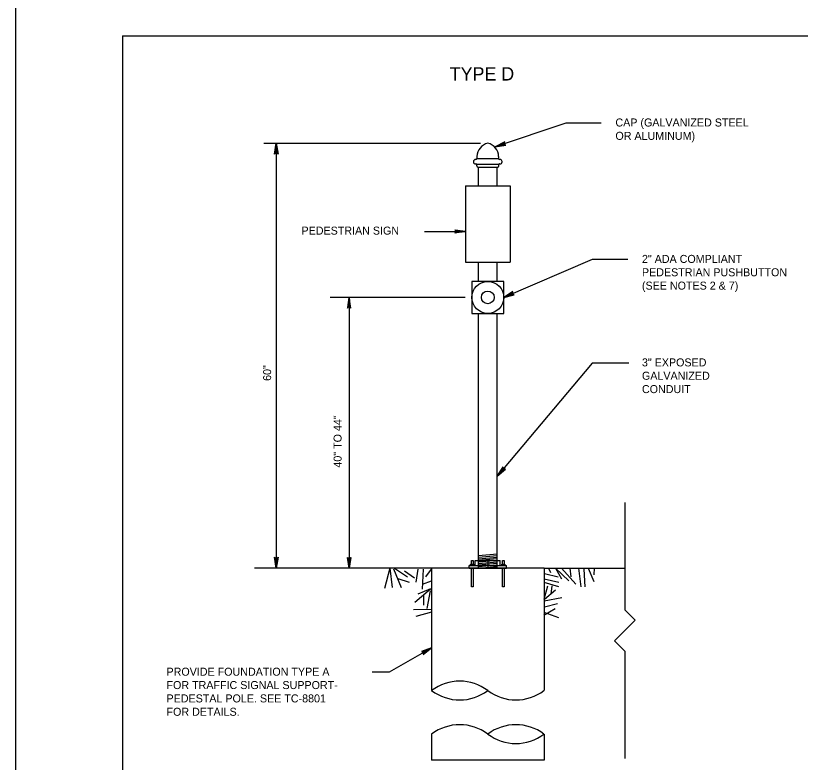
# Model space of a CAD drawing. Extents: x 36 to 940, y -1166 to 1210.
# Drawn here: x 35.9 to 329.9, y -265 to 14.7 of the extents above; entities that cross this region are included whole.
import ezdxf

# ---------------------------------------------------------------- set-up
doc = ezdxf.new("R2010")
doc.units = 0
for name, color, linetype in [('1', 7, 'Continuous'), ('2', 7, 'Continuous'), ('Default', 7, 'Continuous'), ('PLT-BNDY', 7, 'Continuous')]:
    doc.layers.add(name, color=color, linetype=linetype)

msp = doc.modelspace()

# ---------------------------------------------------------------- linework, layer by layer
at = {"layer": '1'}
for p, q in [((75.86, 7.17), (861.86, 7.17)), ((75.86, 7.17), (75.86, -556.83)), ((242.01, -25.54), (215.51, -34.47)), ((255.28, -25.54), (242.01, -25.54)), ((189.11, -66.13), (204.45, -66.13)), ((251.95, -76.64), (218.77, -90.85)), ((265.22, -76.64), (251.95, -76.64)), ((204.34, -90.85), (153.7, -90.85)), ((160.78, -90.85), (160.78, -192.24)), ((251.95, -115.43), (216.31, -157.79)), ((265.61, -115.43), (251.95, -115.43)), ((209.29, -187.54), (216.31, -186.93)), ((209.29, -188.13), (216.31, -187.52)), ((209.29, -188.72), (216.31, -188.1)), ((208.12, -191.3), (208.12, -189.43)), ((208.12, -189.43), (217.48, -189.43)), ((208.12, -191.3), (208.12, -189.43)), ((209.29, -189.3), (216.31, -188.69)), ((209.29, -189.89), (216.31, -189.28)), ((209.29, -190.48), (216.31, -189.86)), ((209.29, -191.06), (216.31, -190.45)), ((209.29, -191.65), (216.31, -191.04)), ((217.48, -191.3), (217.48, -189.43)), ((217.48, -191.3), (217.48, -189.43)), ((191.74, -192.24), (125.38, -192.24)), ((176.04, -192.24), (174.1, -199.82)), ((176.06, -192.32), (176.95, -199.48)), ((177.5, -192.5), (180.35, -199.48)), ((177.84, -192.32), (182.68, -195.53)), ((181.6, -193.21), (185.37, -195.9)), ((186.54, -192.68), (185.83, -197.5)), ((188.52, -192.68), (188.16, -200.19)), ((191.56, -192.68), (189.41, -195.53)), ((233.86, -192.24), (191.74, -192.24)), ((191.74, -192.24), (191.74, -238.1)), ((205.79, -192.24), (205.79, -191.3)), ((205.79, -191.3), (219.81, -191.3)), ((205.79, -192.24), (205.79, -191.3)), ((205.79, -192.24), (219.81, -192.24)), ((209.29, -192.24), (216.31, -191.62)), ((219.81, -192.24), (219.81, -191.3)), ((219.81, -192.24), (219.81, -191.3)), ((233.86, -192.24), (233.86, -238.1)), ((233.86, -192.24), (264.18, -192.24)), ((235.58, -192.24), (236.26, -193.92)), ((238.22, -192.31), (240.37, -196.25)), ((238.22, -192.31), (243.22, -196.96)), ((240.46, -192.24), (245.73, -198.21)), ((243.58, -192.31), (243.93, -195.52)), ((246.8, -192.31), (247.69, -199.28)), ((248.76, -192.67), (249.12, -199.28)), ((250.38, -192.31), (252.52, -197.32)), ((252.69, -192.31), (252.52, -194.82)), ((179.1, -196.08), (183.38, -197.5)), ((233.93, -196.25), (239.47, -197.49)), ((234.1, -194.27), (239.11, -195.52)), ((191.56, -197.15), (188.16, -198.4)), ((233.75, -197.49), (239.29, -199.1)), ((233.93, -203.92), (235.35, -198.92)), ((236.6, -201.96), (236.97, -198.92)), ((191.37, -200.19), (185.47, -205.18)), ((191.37, -200.01), (186.54, -201.97)), ((188.69, -202.51), (188.69, -206.07)), ((191.19, -200.71), (189.94, -207.33)), ((234.1, -203.92), (238.22, -200.36)), ((233.93, -204.46), (240.55, -203.21)), ((234.1, -206.79), (238.93, -205.54)), ((191.74, -207.69), (184.94, -207.87)), ((191.74, -208.76), (185.83, -210.38)), ((233.75, -209.82), (238.04, -207.32)), ((233.75, -208.75), (239.29, -210.71)), ((175.99, -231.06), (191.74, -222.08)), ((169.48, -231.06), (175.99, -231.06)), ((191.74, -254.41), (191.74, -264.15)), ((233.86, -254.41), (233.86, -264.15)), ((233.86, -264.15), (191.74, -264.15))]:
    msp.add_line(p, q, dxfattribs=at)
for points in [[(218.98, -32.79), (218.94, -33.1), (215.51, -34.47), (218.98, -32.79), (219.12, -32.57), (215.51, -34.47), (219.06, -33.47), (219.27, -33.68), (215.51, -34.47), (219.53, -33.79), (219.27, -33.68)], [(200.62, -65.65), (200.76, -65.93), (204.45, -66.13), (200.62, -65.65), (200.42, -65.48), (204.45, -66.13), (200.77, -66.31), (200.63, -66.59), (204.45, -66.13), (200.42, -66.77), (200.63, -66.59)], [(161.26, -94.68), (160.99, -94.53), (160.78, -90.85), (161.26, -94.68), (161.43, -94.87), (160.78, -90.85), (160.6, -94.53), (160.33, -94.66), (160.78, -90.85), (160.15, -94.87), (160.33, -94.66)], [(222.11, -88.92), (222.08, -89.24), (218.77, -90.85), (222.11, -88.92), (222.22, -88.69), (218.77, -90.85), (222.23, -89.59), (222.46, -89.79), (218.77, -90.85), (222.72, -89.88), (222.46, -89.79)], [(218.4, -154.55), (218.52, -154.84), (216.31, -157.79), (218.4, -154.55), (218.4, -154.29), (216.31, -157.79), (218.81, -155.09), (219.11, -155.16), (216.31, -157.79), (219.38, -155.12), (219.11, -155.16)], [(264.18, -167.69), (264.18, -207.82), (268.07, -211.72), (260.28, -219.51), (264.18, -223.41), (264.18, -263.55)], [(161.26, -188.41), (160.99, -188.56), (160.78, -192.24), (161.26, -188.41), (161.43, -188.22), (160.78, -192.24), (160.6, -188.56), (160.33, -188.42), (160.78, -192.24), (160.15, -188.22), (160.33, -188.42)], [(206.66, -190.72), (206.66, -189.43), (207.25, -189.43), (207.25, -190.72)], [(206.66, -191.3), (206.66, -190.72)], [(218.35, -190.72), (218.35, -189.43), (218.94, -189.43), (218.94, -190.72)], [(207.25, -192.24), (207.25, -199.25), (206.66, -199.25), (206.66, -192.24)], [(218.94, -192.24), (218.94, -199.25), (218.35, -199.25), (218.35, -192.24)], [(188.65, -224.37), (188.64, -224.06), (191.74, -222.08), (188.65, -224.37), (188.56, -224.61), (191.74, -222.08), (188.45, -223.72), (188.2, -223.55), (191.74, -222.08), (187.93, -223.49), (188.2, -223.55)]]:
    msp.add_lwpolyline(points, dxfattribs=at)
for points in [[(206.37, -191.3), (206.37, -190.72), (207.54, -190.72), (207.54, -191.3)], [(218.06, -191.3), (218.06, -190.72), (219.23, -190.72), (219.23, -191.3)]]:
    msp.add_lwpolyline(points, close=True, dxfattribs=at)
for centre, start, end in [((202.27, -252.06), 52.9724, 127.0276), ((202.27, -224.14), 232.9724, 307.0276), ((223.33, -224.14), 232.9724, 307.0276), ((202.27, -268.37), 52.9724, 127.0276), ((223.33, -268.37), 52.9724, 127.0276), ((223.33, -240.46), 232.9724, 307.0276)]:
    msp.add_arc(centre, 17.48, start, end, dxfattribs=at)
at = {"layer": '2'}
msp.add_line((212.8, -189.43), (212.8, -192.24), dxfattribs=at)
for points in [[(133.06, -36.96), (133.34, -36.82), (133.54, -33.1), (133.06, -36.96), (132.89, -37.16), (133.54, -33.1), (133.73, -36.81), (134, -36.95), (133.54, -33.1), (134.19, -37.16), (134, -36.95)], [(134.02, -188.38), (133.74, -188.52), (133.54, -192.24), (134.02, -188.38), (134.19, -188.18), (133.54, -192.24), (133.35, -188.52), (133.08, -188.39), (133.54, -192.24), (132.89, -188.18), (133.08, -188.39)]]:
    msp.add_lwpolyline(points, dxfattribs=at)
at = {"layer": 'Default'}
for p, q in [((128.8, -33.09), (210.08, -33.09)), ((133.54, -33.09), (133.54, -192.24)), ((208.74, -38.04), (208.74, -38.78)), ((216.86, -38.04), (216.86, -38.78)), ((208.26, -39.18), (208.32, -39.18)), ((208.42, -40.87), (208.26, -40.87)), ((208.63, -41.62), (208.63, -41.07)), ((216.97, -41.62), (216.97, -41.07)), ((217.34, -40.87), (217.18, -40.87)), ((217.28, -39.18), (217.34, -39.18)), ((218.17, -40.08), (218.17, -39.97)), ((209.05, -42.02), (216.55, -42.02)), ((209.29, -49), (209.29, -42.02)), ((216.31, -49), (216.31, -42.02)), ((204.45, -49), (221.16, -49)), ((204.45, -49), (204.45, -77.65)), ((221.16, -49), (221.16, -77.65)), ((204.45, -77.65), (221.16, -77.65)), ((209.29, -84.88), (209.29, -77.65)), ((216.31, -84.88), (216.31, -77.65)), ((206.83, -96.82), (218.77, -96.82)), ((209.29, -192.24), (209.29, -96.82)), ((216.31, -192.24), (216.31, -96.82))]:
    msp.add_line(p, q, dxfattribs=at)
msp.add_lwpolyline([(218.77, -96.82), (218.77, -84.88), (206.83, -84.88), (206.83, -96.82), (206.83, -96.82)], dxfattribs=at)
for radius in [5.97, 2.39]:
    msp.add_circle((212.8, -90.85), radius, dxfattribs=at)
for centre, major_axis, ratio, start_param, end_param in [((214.17, -38.09), (5.43, 0), 0.952381, 1.825494, 3.132766), ((211.43, -38.09), (5.43, 0), 0.952381, 0.008827, 1.316099), ((208.26, -39.97), (0.833, 0), 0.952381, 1.570796, 3.141593), ((208.26, -40.08), (0.833, 0), 0.952381, 3.141593, 4.712389), ((208.32, -38.78), (0.417, 0), 0.952381, 4.712389, 6.283185), ((208.42, -41.07), (0.208, 0), 0.952381, 0, 1.570796), ((212.88, -40.87), (-4.46, 0), 0.026054, 0.212556, 2.780907), ((212.8, -38.78), (-4.06, 0), 0.012269, 0, 3.141593), ((217.28, -38.78), (0.417, 0), 0.952381, 3.141593, 4.712389), ((217.18, -41.07), (0.208, 0), 0.952381, 1.570796, 3.141593), ((217.34, -39.97), (0.833, 0), 0.952381, 0, 1.570796), ((217.34, -40.08), (0.833, 0), 0.952381, 4.712389, 6.283185), ((209.05, -41.62), (0.417, 0), 0.952381, 3.141593, 4.712389), ((216.55, -41.62), (0.417, 0), 0.952381, 4.712389, 6.283185)]:
    msp.add_ellipse(centre, major_axis=major_axis, ratio=ratio, start_param=start_param, end_param=end_param, dxfattribs=at)
at = {"layer": 'PLT-BNDY'}
msp.add_lwpolyline([(35.86, 22.17), (876.86, 22.17), (876.86, -571.83), (35.86, -571.83)], close=True, dxfattribs=at)

# ---------------------------------------------------------------- texts
at = {"layer": '2'}
for s, height, p in [('TYPE D', 5, (198.53, -9.61)), ('CAP (GALVANIZED STEEL', 3, (260.63, -26.83)), ('OR ALUMINUM)', 3, (260.63, -31.83)), ('PEDESTRIAN SIGN', 3, (142.97, -67.33)), ('2" ADA COMPLIANT', 3, (270.57, -77.93)), ('PEDESTRIAN PUSHBUTTON', 3, (270.57, -82.93)), ('(SEE NOTES 2 & 7)', 3, (270.57, -87.93)), ('3" EXPOSED ', 3, (270.57, -116.69)), ('GALVANIZED', 3, (270.57, -121.69)), ('CONDUIT', 3, (270.57, -126.69)), ('PROVIDE FOUNDATION TYPE A', 3, (92.38, -232.55)), ('FOR TRAFFIC SIGNAL SUPPORT- ', 3, (92.38, -237.55)), ('PEDESTAL POLE. SEE TC-8801 ', 3, (92.38, -242.55)), ('FOR DETAILS.', 3, (92.38, -247.55))]:
    msp.add_text(s, height=height, dxfattribs=at).set_placement(p)
msp.add_text('40" TO 44"', height=3, rotation=90, dxfattribs=at).set_placement((158, -154.6))
at = {"layer": 'Default'}
msp.add_text('60"', height=3, rotation=90, dxfattribs=at).set_placement((131.59, -122.12))

doc.saveas('drawing.dxf')
